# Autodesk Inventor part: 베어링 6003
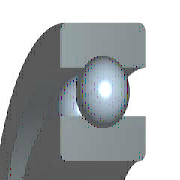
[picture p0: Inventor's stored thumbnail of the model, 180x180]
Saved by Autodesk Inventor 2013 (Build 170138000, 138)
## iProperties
Created: 2012-02
Part Number: 베어링 6003
Material: 강철, 연강
Description: 깊은 그루브 볼 베어링
Document SubType Name: Modeling
Standard: KS B 2023
Designer: mduedu
Standards Organization: KS
Language: ko-KR
Size Designation: 6003 - 17 x 35 x 10
Categories: <MemberInstance><Categories><Category DisplayName="샤프트 부품" InternalName="7f7aeb1f-a693-4053-b835-cee3144e0d98" Mnemonic="SHFT"><Category DisplayName="베어링" Inter
Density: 7.86 g/cm^3
Mass: 39.0276 g
Surface Area: 48.7538 cm^2
Volume: 4.96535 cm^3
IsCustomPart: 1
Author: mduedu
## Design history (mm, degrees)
sketch "스케치" dims "d0" = 4.68 (= -0.26 x WD + 0.26 x BD)
  geometry: L1 (2.66, 13)-(7.34, 13); L2 (5, 13)-(5, 10.66); L3 (5, 13)-(5, 15.34); L4 (3.261, 11.434)-(0, 11.434); L5 (0, 8.5)-(10, 8.5); L6 (3.261, 14.566)-(0, 14.566); L7 (0, 17.5)-(10, 17.5); L8 (10, 8.5)-(10, 11.434); L9 (6.739, 11.434)-(10, 11.434); L10 (6.739, 14.566)-(10, 14.566); L11 (10, 17.5)-(10, 14.566); L12 (-1.4, 0)-(8.4, 0) reference; L13 (0, -0.3)-(0, 5.3) reference
  constraints: 22 end point, 4 point on line, 2 collinear, 2 perpendicular, 2 symmetric about line, 1 midpoint, 1 parallel, 14 other
  dimensions: "d9" = 17 diameter of L5 L12 (= WD); "d11" = 35 diameter of L7 L12 (= BD); "d12" = 10 distance between parallel lines of L8 L13 (= KB); "d13" = 22.868 diameter of L9 L12 (= 0.326 x BD + 0.674 x WD)
revolve "본체" stored, may be unused: angle "d6" = 90 deg
revolve "볼" stored, may be unused: angle "d7" = 90 deg
pattern_circular "IDS_ARRAYBALL[SIMPL:T]" dims angle "d3" = 360 deg
body "Solid1"
fillet "모깎기1" dims "d1" = 0.3 (= KRS)
other parameters: "WD" = 17 [user parameter; used in 5 equation terms], "BD" = 35 [user parameter; used in 5 equation terms], "KB" = 10 [user parameter; used in 1 equation term], "KRS" = 0.3 [user parameter; used in 1 equation term], "d4" = 0, "d5" = 0, "d8" = 0, "d14" = 0, "d15" = 0, "BBA" = 0 [user parameter], "BC0" = 3250000 [user parameter], "BC" = 6050000 [user parameter], "BR" = 17.5 (= 0.5 x BD) [user parameter], "WR" = 8.5 (= 0.5 x WD) [user parameter]
